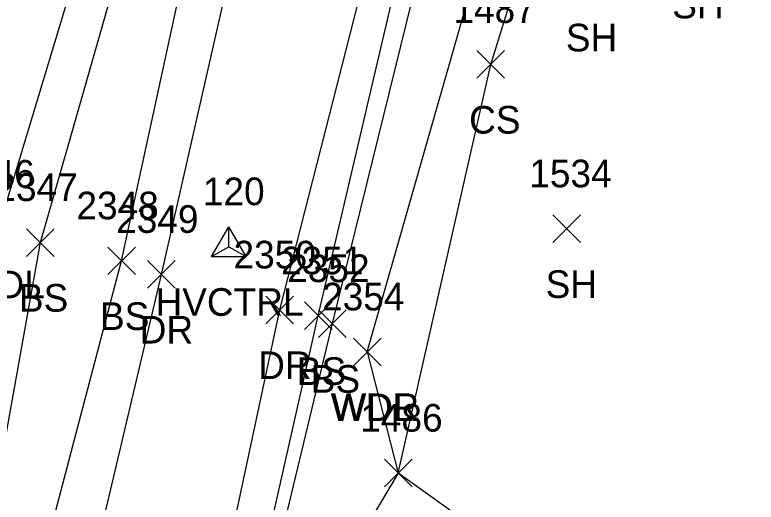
# Model space of a CAD drawing. Extents: x 1761340 to 1763889, y 696770 to 706023.
# Drawn here: x 1761657.7 to 1761711.3, y 700882.9 to 700918.1 of the extents above; entities that cross this region are included whole.
import ezdxf

# ---------------------------------------------------------------- set-up
doc = ezdxf.new("R2010")
doc.units = 0
for name, color, linetype in [('C_A', 7, 'Continuous'), ('C_I', 7, 'Continuous'), ('CPSM', 7, 'Continuous'), ('L_A', 7, 'Continuous'), ('L_I', 7, 'Continuous'), ('L_TIC', 7, 'Continuous'), ('LAWA', 7, 'Continuous'), ('LELB', 7, 'Continuous'), ('R_A', 7, 'Continuous'), ('R_I', 7, 'Continuous'), ('R_TIC', 7, 'Continuous'), ('RDP', 7, 'Continuous')]:
    doc.layers.add(name, color=color, linetype=linetype)

msp = doc.modelspace()

# ---------------------------------------------------------------- linework, layer by layer
at = {"layer": 'CPSM'}
for p, q in [((1761671.947, 700900.653), (1761673.197, 700902.818)), ((1761674.447, 700900.653), (1761673.197, 700902.818)), ((1761673.198, 700901.374), (1761673.197, 700902.818)), ((1761671.947, 700900.653), (1761673.198, 700901.374)), ((1761673.198, 700901.374), (1761673.198, 700901.374)), ((1761673.198, 700901.374), (1761674.447, 700900.653)), ((1761671.947, 700900.653), (1761674.447, 700900.653))]:
    msp.add_line(p, q, dxfattribs=at)
at = {"layer": 'L_TIC'}
for points in [[(1761691.112, 700913.553), (1761693.112, 700915.553)], [(1761693.112, 700913.553), (1761691.112, 700915.553)], [(1761696.593, 700901.665), (1761698.593, 700903.665)], [(1761698.593, 700901.665), (1761696.593, 700903.665)], [(1761658.58, 700900.674), (1761660.58, 700902.674)], [(1761660.58, 700900.674), (1761658.58, 700902.674)], [(1761664.437, 700899.351), (1761666.437, 700901.351)], [(1761666.437, 700899.351), (1761664.437, 700901.351)], [(1761678.654, 700895.376), (1761680.654, 700897.376)], [(1761680.654, 700895.376), (1761678.654, 700897.376)], [(1761679.672, 700894.811), (1761681.672, 700896.811)], [(1761681.672, 700894.811), (1761679.672, 700896.811)], [(1761682.188, 700892.766), (1761684.188, 700894.766)], [(1761684.188, 700892.766), (1761682.188, 700894.766)], [(1761682.188, 700892.766), (1761684.188, 700894.766)], [(1761684.188, 700892.766), (1761682.188, 700894.766)], [(1761684.438, 700884.001), (1761686.438, 700886.001)], [(1761686.438, 700884.001), (1761684.438, 700886.001)]]:
    msp.add_lwpolyline(points, dxfattribs=at)
at = {"layer": 'LAWA'}
for points in [[(1761683.188, 700893.766), (1761693.758, 700930.803), (1761702.559, 700960.086), (1761708.212, 700986.106), (1761709.805, 700994.41), (1761714.454, 701002.915), (1761720.388, 701013.775), (1761724.654, 701022.108), (1761723.358, 701026.155), (1761723.242, 701034.182), (1761732.591, 701076.408), (1761747, 701128.03)], [(1761656.53, 700902.641), (1761667.453, 700938.832)], [(1761683.188, 700893.766), (1761685.438, 700885.001)], [(1761696.403, 700877.132), (1761685.438, 700885.001)]]:
    msp.add_lwpolyline(points, dxfattribs=at)
at = {"layer": 'LELB'}
for points in [[(1761681.301, 700585.517), (1761671.929, 700613.506), (1761667.591, 700648.271), (1761662.956, 700684.404), (1761660.968, 700720.859), (1761660.494, 700762.081), (1761662.811, 700791.593), (1761666.165, 700822.147), (1761669.086, 700835.752), (1761669.554, 700847.216), (1761671.381, 700859.702), (1761679.654, 700896.376), (1761688.232, 700933.044), (1761696.404, 700960.959), (1761706.351, 700997.906), (1761723.358, 701026.155)], [(1761684.453, 700586.471), (1761674.154, 700613.84), (1761669.556, 700648.243), (1761665.944, 700684.581), (1761663.689, 700720.734), (1761662.667, 700762.265), (1761665.109, 700791.249), (1761666.952, 700822.175), (1761669.965, 700835.611), (1761670.376, 700847.091), (1761671.954, 700859.509), (1761680.672, 700895.811), (1761689.739, 700932.613), (1761697.717, 700961.083), (1761707.94, 700997.332), (1761724.654, 701022.108)], [(1761650.668, 700568.581), (1761653.72, 700589.345), (1761656.228, 700611.846), (1761650.783, 700645.878), (1761646.693, 700682.268), (1761643.965, 700721.139), (1761646.185, 700763.151), (1761649.001, 700791.974), (1761651.08, 700826.684), (1761655.56, 700862.863), (1761665.437, 700900.351), (1761673.527, 700937.717), (1761682.384, 700964.347), (1761693.002, 701008.082), (1761690.127, 701015.338), (1761683.006, 701019.111)], [(1761647.361, 700568.693), (1761651.507, 700589.637), (1761652.179, 700611.172), (1761648.147, 700645.92), (1761644.284, 700683.035), (1761641.556, 700721.375), (1761643.749, 700763.66), (1761644.587, 700792.445), (1761648.472, 700827.402), (1761652.737, 700863.508), (1761659.58, 700901.674), (1761670.104, 700938.531), (1761679.505, 700964.488), (1761691.194, 701008.19), (1761682.174, 701016.504)], [(1761685.438, 700885.001), (1761692.112, 700914.553), (1761702.263, 700947.284)], [(1761685.438, 700885.001), (1761680.099, 700876.066)]]:
    msp.add_lwpolyline(points, dxfattribs=at)
at = {"layer": 'R_TIC'}
for points in [[(1761667.314, 700898.372), (1761669.314, 700900.372)], [(1761669.314, 700898.372), (1761667.314, 700900.372)], [(1761675.875, 700895.799), (1761677.875, 700897.799)], [(1761677.875, 700895.799), (1761675.875, 700897.799)]]:
    msp.add_lwpolyline(points, dxfattribs=at)
at = {"layer": 'RDP'}
for points in [[(1761671.259, 700538.434), (1761661.644, 700574.622), (1761657.605, 700611.792), (1761653.176, 700645.742), (1761649.934, 700682.027), (1761646.901, 700721.235), (1761649.099, 700763.058), (1761651.354, 700791.608), (1761653.655, 700826.216), (1761659.48, 700861.884), (1761668.314, 700899.372), (1761676.768, 700936.595), (1761684.872, 700963.935), (1761695.512, 701007.432), (1761695.754, 701009.139), (1761702.957, 701038.717), (1761714.691, 701083.389), (1761730.248, 701133.725)], [(1761685.903, 700541.843), (1761678.398, 700578.094), (1761669.593, 700613.166), (1761665.81, 700647.626), (1761660.309, 700684.319), (1761659.551, 700721.027), (1761658.733, 700762.092), (1761660.802, 700791.687), (1761663.623, 700822.45), (1761666.152, 700836.338), (1761667.517, 700847.08), (1761668.947, 700859.679), (1761676.875, 700896.799), (1761686.16, 700933.202), (1761693.935, 700961.975), (1761704.585, 700998.319), (1761705.06, 700999.037), (1761715.839, 701034.881), (1761727.081, 701077.741), (1761742.289, 701129.681)]]:
    msp.add_lwpolyline(points, dxfattribs=at)

# ---------------------------------------------------------------- texts
at = {"layer": 'C_A'}
msp.add_text('HVCTRL', height=2, dxfattribs=at).set_placement((1761667.891, 700896.374))
at = {"layer": 'C_I'}
msp.add_text('120', height=2, dxfattribs=at).set_placement((1761671.316, 700904.374))
at = {"layer": 'L_A'}
for s, p in [('SH', (1761705.23, 700917.884)), ('SH', (1761697.544, 700915.494)), ('CS', (1761690.553, 700909.553)), ('WDL', (1761653.948, 700897.641)), ('SH', (1761696.081, 700897.665)), ('BS', (1761658.021, 700896.674)), ('BS', (1761663.878, 700895.351)), ('BS', (1761678.095, 700891.376)), ('BS', (1761679.113, 700890.811)), ('WDR', (1761680.551, 700888.766)), ('WDL', (1761680.606, 700888.766))]:
    msp.add_text(s, height=2, dxfattribs=at).set_placement(p)
at = {"layer": 'L_I'}
for s, p in [('1487', (1761689.419, 700917.553)), ('2346', (1761653.216, 700905.641)), ('1534', (1761694.901, 700905.665)), ('2347', (1761656.321, 700904.674)), ('2348', (1761662.178, 700903.351)), ('2351', (1761676.961, 700899.376)), ('2352', (1761677.413, 700898.811)), ('2354', (1761679.929, 700896.766)), ('2354', (1761679.929, 700896.766)), ('1486', (1761682.69, 700888.001))]:
    msp.add_text(s, height=2, dxfattribs=at).set_placement(p)
at = {"layer": 'R_A'}
for p in [(1761666.747, 700894.372), (1761675.308, 700891.799)]:
    msp.add_text('DR', height=2, dxfattribs=at).set_placement(p)
at = {"layer": 'R_I'}
for s, p in [('2349', (1761665.047, 700902.372)), ('2350', (1761673.529, 700899.799))]:
    msp.add_text(s, height=2, dxfattribs=at).set_placement(p)

doc.saveas('drawing.dxf')
